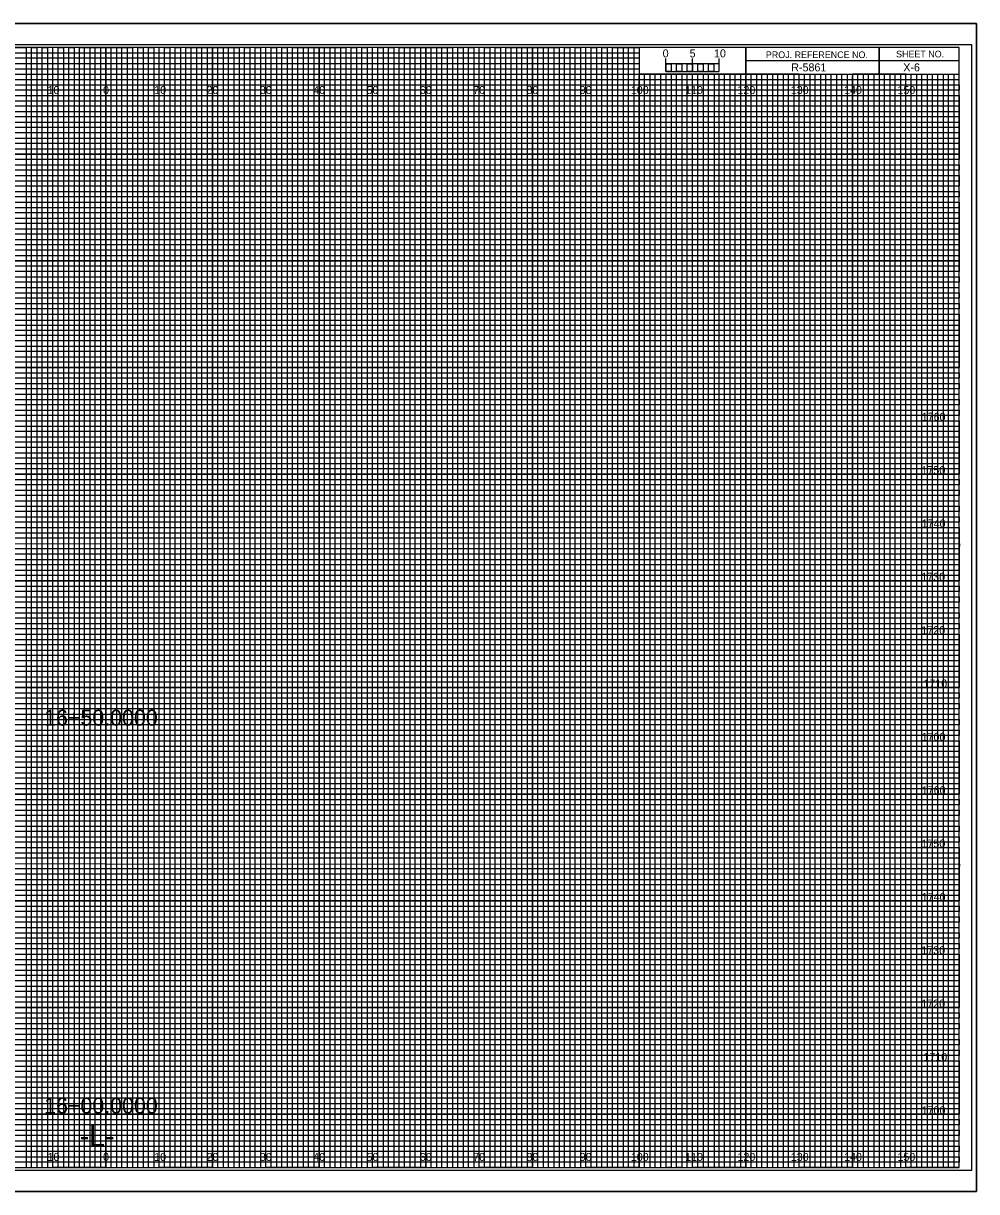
# Model space of a CAD drawing. Extents: x -419 to 4739, y -630 to 13534.
# Drawn here: x 144.5 to 323.3, y 1095.5 to 1314.5 of the extents above; entities that cross this region are included whole.
import ezdxf

# ---------------------------------------------------------------- set-up
doc = ezdxf.new("R2010")
doc.units = 0
for name, color, linetype in [('Old_Level_1', 7, 'Continuous'), ('Old_Level_62', 7, 'Continuous'), ('Pattern 1', 7, 'Continuous'), ('Pattern 18', 7, 'Continuous'), ('Pattern 4', 7, 'Continuous'), ('Pattern 5', 7, 'Continuous'), ('Prop Dimension', 7, 'Continuous'), ('Prop Horizontal Alignment', 7, 'Continuous'), ('Prop PHM Label Text', 7, 'Continuous'), ('Prop PHM Label Text White', 7, 'Continuous'), ('Prop PHM Roadway Shape', 7, 'Continuous'), ('Prop PHM White Shape', 7, 'Continuous'), ('Raster_Level_0', 7, 'Continuous'), ('Scratch_Level_0', 7, 'Continuous'), ('Scratch_Level_2', 7, 'Continuous'), ('Scratch_Level_3', 7, 'Continuous'), ('Scratch_Level_5', 7, 'Continuous')]:
    doc.layers.add(name, color=color, linetype=linetype)

msp = doc.modelspace()

# ---------------------------------------------------------------- linework, layer by layer
at = {"layer": 'Old_Level_62'}
for p, q in [((305, 1310), (305, 1305)), ((305, 1305), (305, 1310)), ((280, 1307.5), (280, 1305)), ((320, 1307.49), (280, 1307.49)), ((280, 1305), (320, 1305))]:
    msp.add_line(p, q, dxfattribs=at)
for points in [[(320, 1310), (0, 1310), (0, 1100), (320, 1100)], [(280, 1310), (260, 1310), (260, 1305.03), (280, 1305.03)], [(320, 1310), (280, 1310), (280, 1305), (320, 1305)]]:
    msp.add_lwpolyline(points, close=True, dxfattribs=at)
at = {"layer": 'Pattern 18'}
for points in [[(-13.4, 1095.5), (323.3, 1095.5), (323.3, 1314.5), (-13.4, 1314.5)], [(-13.4, 1314.5), (323.3, 1314.5), (323.3, 1095.5), (-13.4, 1095.5)]]:
    msp.add_lwpolyline(points, close=True, dxfattribs=at)
at = {"layer": 'Pattern 4'}
for p, q in [((0, 1309), (260, 1309)), ((260, 1307.98), (0, 1307.98)), ((260, 1309), (260, 1307.98)), ((0, 1307), (260, 1307)), ((260, 1305.89), (0, 1305.89)), ((260, 1307), (260, 1305.89)), ((0, 1304), (320, 1304))]:
    msp.add_line(p, q, dxfattribs=at)
for points in [[(0, 1303), (270, 1303), (320, 1303), (320, 1302), (0, 1302)], [(0, 1301), (320, 1301), (320, 1299), (0, 1299)], [(0, 1298), (320, 1298), (320, 1297), (0, 1296.98)], [(0, 1296), (320, 1296), (320, 1294), (0, 1294)], [(0, 1293), (320, 1293), (320, 1292), (0, 1292)], [(0, 1291), (320, 1291), (320, 1289), (0, 1289)], [(0, 1288), (320, 1288), (320, 1287), (0, 1287)], [(0, 1286), (320, 1286), (320, 1284), (0, 1284)], [(0, 1283), (320, 1283), (320, 1282), (0, 1282)], [(0, 1281), (320, 1281), (320, 1279), (0, 1279)], [(0, 1278), (320, 1278), (320, 1277), (0, 1277)], [(0, 1276), (320, 1276), (320, 1273.95), (320, 1273), (320, 1272), (0, 1272)], [(0, 1274), (320, 1274), (320, 1273), (0, 1273)], [(0, 1271), (320, 1271), (320, 1269), (0, 1269.03)], [(0, 1269.03), (320, 1269), (320, 1268), (0, 1268)], [(0, 1267), (320, 1267), (320, 1266), (0, 1266)], [(0, 1264), (320, 1264), (320, 1263), (0, 1263)], [(0, 1262), (320, 1262), (320, 1261), (0, 1261)], [(-0.07, 1258.89), (320, 1258.89), (320, 1257.88), (-0.07, 1257.88)], [(0, 1257), (320, 1257), (320, 1256), (0, 1256)], [(0, 1254), (320, 1254), (320, 1253), (0, 1253)], [(0, 1252), (320, 1252), (320, 1251), (0, 1251)], [(0, 1249), (320, 1249), (320, 1248), (0, 1248)], [(0, 1247), (320, 1247), (320, 1246), (0, 1246)], [(0, 1244), (320, 1244), (320, 1243), (0, 1243)], [(0, 1242), (320, 1242), (320, 1241), (0, 1241)], [(0, 1239), (320, 1239), (319.99, 1237.98), (0, 1238)], [(0, 1237), (320, 1237), (320, 1236), (0, 1236)], [(0, 1234), (320, 1234), (320, 1233), (0, 1233)], [(0, 1232), (320, 1232), (320, 1231), (0, 1231)], [(0, 1229), (320, 1229), (320, 1228), (0, 1228)], [(0, 1227), (320, 1227), (320, 1226), (0, 1226)], [(0, 1224), (320, 1224), (320, 1223), (0, 1223)], [(0, 1222), (320, 1222), (320, 1221), (0, 1221)], [(0, 1219), (320, 1219), (320, 1218), (0, 1218)], [(0, 1216.99), (320.07, 1216.91), (320, 1216), (0, 1216)], [(0, 1214), (320, 1214), (320, 1213), (0, 1213)], [(0, 1212), (320, 1212), (320, 1211), (0, 1211)], [(0, 1209), (320, 1209), (320, 1208), (0, 1208)], [(0, 1207), (320, 1207), (320, 1206), (0, 1206)], [(0, 1204), (320, 1204), (320, 1203), (0, 1203)], [(0, 1202), (320, 1202), (320, 1201), (0, 1201)], [(0, 1199), (320, 1199), (320, 1198), (0, 1198)], [(0, 1197), (320, 1197), (320, 1196), (0, 1196)], [(0, 1194), (320, 1194), (320, 1193), (0, 1193)], [(0, 1192), (320, 1192), (320, 1191), (0, 1191)], [(0, 1189), (320, 1189), (320, 1188), (0, 1188)], [(0, 1187), (320, 1187), (320, 1186), (0, 1186)], [(0, 1184), (320, 1184), (320, 1183), (0, 1183)], [(0, 1182), (320, 1182), (320, 1181), (0, 1181)], [(0, 1179), (320, 1179), (319.99, 1177.98), (0, 1178)], [(0, 1177), (320, 1177), (320, 1176), (0, 1176)], [(0, 1174), (320, 1174), (320, 1173), (0, 1173)], [(0, 1172), (320, 1172), (320, 1171), (0, 1171)], [(0, 1169), (320, 1169), (320, 1168), (0, 1168)], [(0, 1167), (320, 1167), (320, 1166), (0, 1166)], [(0, 1164), (320, 1164), (320, 1163), (0, 1163)], [(0, 1162), (320, 1162), (320, 1161), (0, 1161)], [(0, 1159), (320, 1159), (320, 1158), (0, 1158)], [(0, 1156.99), (320.07, 1156.91), (320, 1156), (0, 1156)], [(0, 1154), (320, 1154), (320, 1153), (0, 1153)], [(0, 1152), (320, 1152), (320, 1151), (0, 1151)], [(0, 1149), (320, 1149), (320, 1148), (0, 1148)], [(0, 1147), (320, 1147), (320, 1146), (0, 1146)], [(0, 1144), (320, 1144), (320, 1143), (0, 1143)], [(0, 1142), (320, 1142), (320, 1141), (0, 1141)], [(0, 1139), (320, 1139), (320, 1138), (0, 1138)], [(0, 1137), (320, 1137), (320, 1136), (0, 1136)], [(0, 1134), (320, 1134), (320, 1133), (0, 1133)], [(0, 1132), (320, 1132), (320, 1131), (0, 1131)], [(0, 1129), (320, 1129), (320, 1128), (0, 1128)], [(0, 1127), (320, 1127), (320, 1126), (0, 1126)], [(0, 1124), (320, 1124), (320, 1123), (0, 1123)], [(0, 1122), (320, 1122), (320, 1121), (0, 1121)], [(0, 1119), (320, 1119), (320, 1118), (0, 1118)], [(0, 1117), (320, 1117), (320, 1116), (0, 1116)], [(0, 1114), (320, 1114), (320, 1113), (0, 1113)], [(0, 1112), (320, 1112), (320, 1111), (0, 1111)], [(0, 1109), (320, 1109), (320, 1108), (0, 1108)], [(0, 1107), (320, 1107), (320, 1106), (0, 1106)], [(0, 1104), (320, 1104), (320, 1103), (0, 1103)], [(0, 1102), (320, 1102), (320, 1101), (0, 1101)]]:
    msp.add_lwpolyline(points, dxfattribs=at)
at = {"layer": 'Pattern 5'}
for p, q in [((323.3, 1314.5), (-13.4, 1314.5)), ((-13.4, 1095.5), (323.3, 1095.5))]:
    msp.add_line(p, q, dxfattribs=at)
at = {"layer": 'Prop Dimension'}
for p, q in [((267, 1305), (266.01, 1305)), ((266.01, 1305), (266.01, 1100)), ((267, 1100), (267, 1305)), ((269, 1305), (268, 1305)), ((268, 1305), (268, 1100)), ((269, 1100), (269, 1305)), ((266.01, 1100), (265, 1100)), ((268, 1100), (267, 1100))]:
    msp.add_line(p, q, dxfattribs=at)
for points in [[(145, 1100), (146, 1100), (146, 1310), (147, 1310), (147, 1100)], [(147, 1100), (148, 1100), (148, 1310), (149, 1310), (149, 1100)], [(150, 1100), (151, 1100), (151, 1310), (152, 1310), (152, 1100)], [(152, 1100), (153, 1100), (153, 1310), (154, 1310), (154, 1100)], [(155, 1100), (156, 1100), (156, 1310), (157, 1310), (157, 1100)], [(157, 1100), (158, 1100), (158, 1310), (159, 1310), (159, 1100)], [(160, 1100), (161, 1100), (161, 1310), (162, 1310), (162, 1100)], [(162, 1100), (163, 1100), (163, 1310), (164, 1310), (164, 1100)], [(165, 1100), (166, 1100), (166, 1310), (167, 1310), (167, 1100)], [(167, 1100), (168, 1100), (168, 1310), (169, 1310), (169, 1100)], [(170, 1100), (171, 1100), (171, 1310), (172, 1310), (172, 1100)], [(172, 1100), (173, 1100), (173, 1310), (174, 1310), (174, 1100)], [(175, 1100), (176, 1100), (176, 1310), (177, 1310), (177, 1100)], [(177, 1100), (178, 1100), (178, 1310), (179, 1310), (179, 1100)], [(180, 1100), (181, 1100), (181, 1310), (182, 1310), (182, 1100)], [(182, 1100), (183, 1100), (183, 1310), (184, 1310), (184, 1100)], [(185, 1100), (186, 1100), (186, 1310), (187, 1310), (187, 1100)], [(187, 1100), (188, 1100), (188, 1310), (189, 1310), (189, 1100)], [(190, 1100), (191, 1100), (191, 1310), (192, 1310), (192, 1100)], [(192, 1100), (193, 1100), (193, 1310), (194, 1310), (194, 1100)], [(195, 1100), (196, 1100), (196, 1310), (197, 1310), (197, 1100)], [(197, 1100), (198, 1100), (198, 1310), (199, 1310), (199, 1100)], [(200, 1100), (201, 1100), (201, 1310), (202, 1310), (202, 1100)], [(202, 1100), (203, 1100), (203, 1310), (204, 1310), (204, 1100)], [(205, 1100), (206, 1100), (206, 1310), (207, 1310), (207, 1100)], [(207, 1100), (208, 1100), (208, 1310), (209, 1310), (209, 1100)], [(210, 1100), (211, 1100), (211, 1310), (212, 1310), (212, 1100)], [(212, 1100), (213, 1100), (213, 1310), (214, 1310), (214, 1100)], [(215, 1100), (216, 1100), (216, 1310), (217, 1310), (217, 1100)], [(217, 1100), (218, 1100), (218, 1310), (219, 1310), (219, 1100)], [(220, 1100), (221, 1100), (221, 1310), (222, 1310), (222, 1100)], [(222, 1100), (223, 1100), (223, 1310), (224, 1310), (224, 1100)], [(225, 1100), (226, 1100), (226, 1310), (227, 1310), (227, 1100)], [(227, 1100), (228, 1100), (228, 1310), (229, 1310), (229, 1100)], [(230, 1100), (231, 1100), (231, 1310), (232, 1310), (232, 1100)], [(232, 1100), (233, 1100), (233, 1310), (234, 1310), (234, 1100)], [(235, 1100), (236, 1100), (236, 1310), (237, 1310), (237, 1100)], [(237, 1100), (238, 1100), (238, 1310), (239, 1310), (239, 1100)], [(240, 1100), (241, 1100), (241, 1310), (242, 1310), (242, 1100)], [(242, 1100), (243, 1100), (243, 1310), (244, 1310), (244, 1100)], [(245, 1100), (246, 1100), (246, 1310), (247, 1310), (247, 1100)], [(247, 1100), (248, 1100), (248, 1310), (249, 1310), (249, 1100)], [(250, 1100), (251, 1100), (251, 1310), (252, 1310), (252, 1100)], [(252, 1100), (253, 1100), (253, 1310), (254, 1310), (254, 1100)], [(255, 1100), (256, 1100), (256, 1310), (257, 1310), (257, 1100)], [(257, 1100), (258, 1100), (258, 1310), (259, 1310), (259, 1100)], [(260, 1100), (261, 1100), (261, 1305), (262.02, 1305), (262.02, 1100)], [(262, 1100), (263, 1100), (263, 1305), (263.99, 1305), (263.99, 1100)], [(270, 1100), (270.98, 1100), (270.98, 1305), (272, 1305), (272, 1100)], [(272, 1100), (273, 1100), (273, 1305), (274.05, 1305), (274.05, 1100)], [(275, 1100), (276, 1100), (276, 1305), (277, 1305), (277, 1100)], [(277, 1100), (278, 1100), (278, 1305), (279, 1305), (279, 1100)], [(280, 1100), (281, 1100), (281, 1305), (282, 1305), (282, 1100)], [(282, 1100), (283, 1100), (283, 1305), (284, 1305), (284, 1100)], [(285, 1100), (286, 1100), (286, 1305), (287, 1305), (287, 1100)], [(287, 1100), (288, 1100), (288, 1305), (289, 1305), (289, 1100)], [(290, 1100), (291, 1100), (291, 1305), (292, 1305), (292, 1100)], [(292, 1100), (293, 1100), (293, 1305), (294, 1305), (294, 1100)], [(295, 1100), (296, 1100), (296, 1305), (297, 1305), (297, 1100)], [(297, 1100), (298, 1100), (298, 1305), (299, 1305), (299, 1100)], [(300, 1100), (301, 1100), (301, 1305), (302, 1305), (302, 1100)], [(302, 1100), (303, 1100), (303, 1305), (304, 1305), (304, 1100)], [(305, 1100), (306, 1100), (306, 1305), (307, 1305), (307, 1100)], [(307, 1100), (308, 1100), (308, 1305), (309, 1305), (309, 1100)], [(310, 1100), (311, 1100), (311, 1305), (312, 1305), (312, 1100)], [(312, 1100), (313, 1100), (313, 1305), (314, 1305), (314, 1100)], [(315, 1100), (316, 1100), (316, 1305), (317, 1305), (317, 1100)], [(317, 1100), (318, 1100), (318, 1305), (319, 1305), (319, 1100)]]:
    msp.add_lwpolyline(points, dxfattribs=at)
at = {"layer": 'Prop Horizontal Alignment'}
for points in [[(135, 1310), (145, 1310), (145, 1100), (155, 1100), (155, 1310), (165, 1310), (165, 1100), (175, 1100), (175, 1310), (185, 1310), (185, 1100), (195, 1100), (195, 1310), (205, 1310), (205, 1100), (215, 1100), (215, 1310), (225, 1310), (225, 1100), (235, 1100), (235, 1310), (245, 1310), (245, 1100), (255, 1100), (255, 1310), (259.93, 1310), (260, 1310), (260, 1305), (264.99, 1305), (264.99, 1100), (275, 1100), (275, 1305), (285, 1305), (285, 1100), (295, 1100), (295, 1305), (305, 1305), (305, 1100), (315, 1100), (315, 1305)], [(0, 1305), (275, 1305)], [(0, 1285), (320, 1285), (320, 1295), (0, 1295)], [(0, 1265), (320, 1265), (320, 1275), (0, 1275)], [(0, 1245), (320, 1245), (320, 1255), (0, 1255)], [(0, 1225), (320, 1225), (320, 1235), (0, 1235)], [(0, 1205), (320, 1205), (320, 1215), (0, 1215)], [(0, 1185), (320, 1185), (320, 1195), (0, 1195)], [(0, 1165), (320, 1165), (320, 1175), (0, 1175)], [(0, 1145), (320, 1145), (320, 1155), (0, 1155)], [(0, 1125), (320, 1125), (320, 1135), (0, 1135)], [(0, 1105), (320, 1105), (320, 1115), (0, 1115)]]:
    msp.add_lwpolyline(points, dxfattribs=at)
at = {"layer": 'Prop PHM Label Text'}
for p, q in [((265, 1305.49), (265, 1307.9)), ((265, 1306.9), (265, 1307.9)), ((270, 1305.49), (270, 1307.9)), ((275, 1305.49), (275, 1307.9)), ((275, 1306.9), (275, 1307.9))]:
    msp.add_line(p, q, dxfattribs=at)
for points in [[(275, 1306.9), (265, 1306.9), (265, 1305.49), (275, 1305.49)], [(265, 1306.9), (266, 1306.9), (266, 1305.49), (265, 1305.49)], [(267, 1306.9), (268, 1306.9), (268, 1305.49), (267, 1305.49)], [(269, 1306.9), (270, 1306.9), (270, 1305.49), (269, 1305.49)], [(271, 1306.9), (272, 1306.9), (272, 1305.49), (271, 1305.49)], [(273, 1306.9), (274, 1306.9), (274, 1305.49), (273, 1305.49)]]:
    msp.add_lwpolyline(points, close=True, dxfattribs=at)
at = {"layer": 'Scratch_Level_0'}
for p, q in [((150, 1100), (150, 1310)), ((160, 1100), (160, 1310)), ((170, 1100), (170, 1310)), ((180, 1100), (180, 1310)), ((190, 1100), (190, 1310)), ((200, 1100), (200, 1310)), ((210, 1100), (210, 1310)), ((220, 1100), (220, 1310)), ((230, 1100), (230, 1310)), ((240, 1100), (240, 1310)), ((250, 1100), (250, 1310)), ((260, 1100), (260, 1304.69)), ((270, 1100), (270, 1304.69)), ((280, 1100), (280, 1304.69)), ((290, 1100), (290, 1304.69)), ((300, 1100), (300, 1304.69)), ((310, 1100), (310, 1304.69)), ((0, 1300), (320, 1300)), ((0, 1290), (320, 1290)), ((0, 1280), (320, 1280)), ((0, 1270), (320, 1270)), ((0, 1260), (320, 1260)), ((0, 1250), (320, 1250)), ((0, 1240), (320, 1240)), ((0, 1230), (320, 1230)), ((0, 1220), (320, 1220)), ((0, 1210), (320, 1210)), ((0, 1200), (320, 1200)), ((0, 1190), (320, 1190)), ((0, 1180), (320, 1180)), ((0, 1170), (320, 1170)), ((0, 1160), (320, 1160)), ((0, 1150), (320, 1150)), ((0, 1140), (320, 1140)), ((0, 1130), (320, 1130)), ((0, 1120), (320, 1120)), ((0, 1110), (320, 1110))]:
    msp.add_line(p, q, dxfattribs=at)
at = {"layer": 'Scratch_Level_3'}
for p, q in [((150, 1310), (140, 1310)), ((150, 1100), (150, 1310)), ((170, 1310), (160, 1310)), ((160, 1310), (160, 1100)), ((170, 1100), (170, 1310)), ((190, 1310), (180, 1310)), ((180, 1310), (180, 1100)), ((190, 1100), (190, 1310)), ((210, 1310), (200, 1310)), ((200, 1310), (200, 1100)), ((210, 1100), (210, 1310)), ((230, 1310), (220, 1310)), ((220, 1310), (220, 1100)), ((230, 1100), (230, 1310)), ((250, 1310), (240, 1310)), ((240, 1310), (240, 1100)), ((250, 1100), (250, 1310)), ((260, 1310), (260, 1100)), ((270, 1100), (270, 1305)), ((290, 1305), (280, 1305)), ((280, 1305), (280, 1100)), ((290, 1100), (290, 1305)), ((310, 1305), (300, 1305)), ((300, 1305), (300, 1100)), ((310, 1100), (310, 1305)), ((160, 1100), (150, 1100)), ((180, 1100), (170, 1100)), ((200, 1100), (190, 1100)), ((220, 1100), (210, 1100)), ((240, 1100), (230, 1100)), ((260, 1100), (250, 1100)), ((280, 1100), (270, 1100)), ((300, 1100), (290, 1100)), ((320, 1100), (310, 1100)), ((320, 1100), (320, 1100))]:
    msp.add_line(p, q, dxfattribs=at)
for points in [[(0, 1300), (320, 1300), (320, 1290), (0, 1290)], [(0, 1280), (320, 1280), (320, 1270), (0, 1270)], [(0, 1260), (320, 1260), (320, 1250), (0, 1250)], [(0, 1240), (320, 1240), (320, 1230), (0, 1230)], [(0, 1220), (320, 1220), (320, 1210), (0, 1210)], [(0, 1200), (320, 1200), (320, 1190), (0, 1190)], [(0, 1180), (320, 1180), (320, 1170), (0, 1170)], [(0, 1160), (320, 1160), (320, 1150), (0, 1150)], [(0, 1140), (320, 1140), (320, 1130), (0, 1130)], [(0, 1120), (320, 1120), (320, 1110), (0, 1110)]]:
    msp.add_lwpolyline(points, dxfattribs=at)
at = {"layer": 'Scratch_Level_5'}
msp.add_lwpolyline([(-10.8, 1099.5), (322.4, 1099.5), (322.4, 1310.5), (-10.8, 1310.5)], close=True, dxfattribs=at)

# ---------------------------------------------------------------- texts
at = {"layer": 'Old_Level_1'}
for s, p in [('5', (269.47, 1308.12)), ('10', (274.04, 1308.12))]:
    msp.add_text(s, height=1.5, dxfattribs=at).set_placement(p)
at = {"layer": 'Old_Level_62'}
for s, p in [('PROJ. REFERENCE NO.', (283.77, 1307.99)), ('SHEET NO.', (308.19, 1308.12))]:
    msp.add_text(s, height=1.25, dxfattribs=at).set_placement(p)
at = {"layer": 'Pattern 1'}
for s, p in [('1760', (313, 1240)), ('1750', (312.96, 1230)), ('1740', (313, 1220)), ('1730', (312.92, 1210)), ('1720', (312.93, 1200)), ('1710', (313.31, 1190)), ('1700', (312.98, 1180)), ('1760', (313, 1170)), ('1750', (312.96, 1160)), ('1740', (313, 1150)), ('1730', (312.92, 1140)), ('1720', (312.93, 1130)), ('1710', (313.31, 1120)), ('1700', (312.98, 1110))]:
    msp.add_text(s, height=1.5, dxfattribs=at).set_placement(p)
at = {"layer": 'Prop PHM Label Text'}
msp.add_text('0', height=1.5, dxfattribs=at).set_placement((264.41, 1308.12))
at = {"layer": 'Prop PHM Label Text White'}
msp.add_text('X-6', height=1.5, dxfattribs=at).set_placement((309.54, 1305.5))
at = {"layer": 'Prop PHM Roadway Shape'}
msp.add_text('R-5861', height=1.5, dxfattribs=at).set_placement((288.53, 1305.5))
at = {"layer": 'Prop PHM White Shape'}
msp.add_text('-L-', height=4, dxfattribs=at).set_placement((155.06, 1104))
at = {"layer": 'Raster_Level_0'}
for s, p in [('10', (149.04, 1301.25)), ('0', (159.45, 1301.25)), ('0', (159.45, 1301.25)), ('10', (169.04, 1301.25)), ('20', (178.86, 1301.25)), ('30', (188.86, 1301.25)), ('40', (198.86, 1301.25)), ('50', (208.86, 1301.25)), ('60', (218.86, 1301.25)), ('70', (228.86, 1301.25)), ('80', (238.86, 1301.25)), ('90', (248.86, 1301.25)), ('100', (258.44, 1301.25)), ('110', (268.62, 1301.25)), ('120', (278.44, 1301.25)), ('130', (288.44, 1301.25)), ('140', (298.44, 1301.25)), ('150', (308.44, 1301.25)), ('10', (149.04, 1101.25)), ('0', (159.45, 1101.25)), ('0', (159.45, 1101.25)), ('10', (169.04, 1101.25)), ('20', (178.86, 1101.25)), ('30', (188.86, 1101.25)), ('40', (198.86, 1101.25)), ('50', (208.86, 1101.25)), ('60', (218.86, 1101.25)), ('70', (228.86, 1101.25)), ('80', (238.86, 1101.25)), ('90', (248.86, 1101.25)), ('100', (258.44, 1101.25)), ('110', (268.62, 1101.25)), ('120', (278.44, 1101.25)), ('130', (288.44, 1101.25)), ('140', (298.44, 1101.25)), ('150', (308.44, 1101.25))]:
    msp.add_text(s, height=1.5, dxfattribs=at).set_placement(p)
at = {"layer": 'Scratch_Level_2'}
for s, p in [('16+50.0000', (148.4, 1182.85)), ('16+00.0000', (148.4, 1110.13))]:
    msp.add_text(s, height=3, dxfattribs=at).set_placement(p)

doc.saveas('drawing.dxf')
